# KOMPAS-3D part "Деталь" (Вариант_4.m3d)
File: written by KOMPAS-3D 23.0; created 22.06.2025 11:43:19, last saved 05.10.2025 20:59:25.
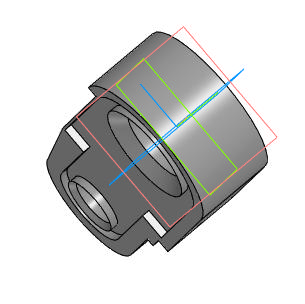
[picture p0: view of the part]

Document properties: Автор: admin; Организация: MGTU; Полное имя файла: C:\Users\ssafo\OneDrive\Desktop\ЦД_Грант\Решенные варианты\Вариант_4.m3d

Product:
- Part/product: Деталь
    Масса: 1.329474
    Форматы листов документа: A4

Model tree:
1. Эскиз:1
2. Элемент выдавливания:1
     Расстояние 1 = 15; Расстояние 2 = 15
3. Эскиз:2  (with: Элемент выдавливания:1)
4. Эскиз:6  (with: Элемент выдавливания:1)
5. Элемент выдавливания:6
     Расстояние 2 = 20
6. Фаска:7  (with: Элемент выдавливания:6)
     Угол = 45; Длина 1 = 0.5; Длина 2 = 0.5
7. Элемент выдавливания:7
     Расстояние 2 = 3
8. Эскиз:8  (with: Элемент выдавливания:7)
9. Элемент выдавливания:9
     Расстояние 1 = 3
10. Эскиз:9  (with: Элемент выдавливания:7, Элемент выдавливания:1)
11. Элемент выдавливания:10
     Расстояние 1 = 3
12. Эскиз:10  (with: Элемент выдавливания:9)
13. Эскиз:11  (with: Элемент выдавливания:10)
14. Эскиз:12  (with: Элемент выдавливания:10, Элемент выдавливания:1)
15. Зеркальный массив:8
16. Экземпляр ( 1 )
17. Экземпляр ( 2 )  (with: Элемент выдавливания:7)
18. Зеркальный массив:9  (with: Экземпляр ( 1 ), Экземпляр ( 2 ), Элемент выдавливания:9, Элемент выдавливания:10)
19. Элемент выдавливания:14
20. Элемент выдавливания:15
21. Фаска:12  (with: Элемент выдавливания:14)
     Угол = 45; Длина 1 = 5; Длина 2 = 5
22. Фаска:13  (with: Элемент выдавливания:15)
     Угол = 45; Длина 1 = 2; Длина 2 = 2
